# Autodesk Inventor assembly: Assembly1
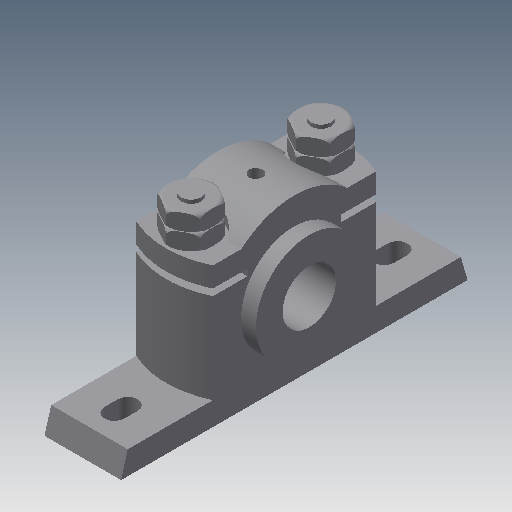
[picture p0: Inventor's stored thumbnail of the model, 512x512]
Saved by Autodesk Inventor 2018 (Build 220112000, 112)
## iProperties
Created: 2016-03
Part Number: Assembly1
Document SubType Name: Assembly
Designer: Sandeep
Author: Sandeep
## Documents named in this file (7)
- E:\_Deepak\Inventor\Autodesk Inventor_2017_Project\Resources\Inventor_2017_tut\c13_Inv_tut_2017\c13-tut01-inv\Plummer block\Assembly1.iam
- E:\_Deepak\Inventor\Autodesk Inventor_2017_Project\Resources\Inventor_2017_tut\c13_Inv_tut_2017\c13-tut01-inv\Plummer block\Casting.ipt
- E:\_Deepak\Inventor\Autodesk Inventor_2017_Project\Resources\Inventor_2017_tut\c13_Inv_tut_2017\c13-tut01-inv\Plummer block\Brasses.ipt
- E:\_Deepak\Inventor\Autodesk Inventor_2017_Project\Resources\Inventor_2017_tut\c13_Inv_tut_2017\c13-tut01-inv\Plummer block\Cap.ipt
- E:\_Deepak\Inventor\Autodesk Inventor_2017_Project\Resources\Inventor_2017_tut\c13_Inv_tut_2017\c13-tut01-inv\Plummer block\Bolt.ipt
- E:\_Deepak\Inventor\Autodesk Inventor_2017_Project\Resources\Inventor_2017_tut\c13_Inv_tut_2017\c13-tut01-inv\Plummer block\Nut.ipt
- E:\_Deepak\Inventor\Autodesk Inventor_2017_Project\Resources\Inventor_2017_tut\c13_Inv_tut_2017\c13-tut01-inv\Plummer block\Lock Nut.ipt
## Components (9 placed, 6 different names)
1. Casting:1 — Mate:1, Mate:2, Insert:1, Insert:2, Angle:1, Angle:2
2. Brasses:1 — Mate:1, Mate:2, Mate:3, Mate:4
3. Cap:1 — Mate:3, Mate:4, Insert:3, Insert:5
4. Bolt:1 — Insert:1, Angle:1
5. Bolt:2 — Insert:2, Angle:2
6. Nut:1 — Insert:3, Insert:4
7. Nut:2 — Insert:5, Insert:6
8. Lock Nut:1 — Insert:4
9. Lock Nut:2 — Insert:6
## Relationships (12: Insert 6, Mate 4, Angle 2)
- Mate:1: Casting:1 ↔ Brasses:1
- Mate:2: Casting:1 ↔ Brasses:1
- Mate:3: Brasses:1 ↔ Cap:1
- Mate:4: Brasses:1 ↔ Cap:1
- Insert:1: Casting:1 ↔ Bolt:1
- Insert:2: Casting:1 ↔ Bolt:2
- Angle:1: Casting:1 ↔ Bolt:1
- Angle:2: Casting:1 ↔ Bolt:2
- Insert:3: Cap:1 ↔ Nut:1
- Insert:4: Nut:1 ↔ Lock Nut:1
- Insert:5: Cap:1 ↔ Nut:2
- Insert:6: Nut:2 ↔ Lock Nut:2
